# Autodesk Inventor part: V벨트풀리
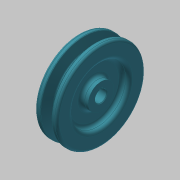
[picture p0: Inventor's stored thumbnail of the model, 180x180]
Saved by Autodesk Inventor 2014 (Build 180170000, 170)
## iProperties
Created: 2015-11
Part Number: V벨트풀리
Material: 강철, 탄소
Document SubType Name: Modeling
Designer: mduedu
Density: 1 g/cm^3
Appearance: Cadet Blue
Author: mduedu
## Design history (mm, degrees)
sketch "스케치1"
  geometry: L1 (-9.5, 0)-(9.5, 0); L2 (0, 0)-(0, 37.7); L3 (-4.825, 37.7)-(-9.5, 37.7); L4 (-9.5, 37.7)-(-9.5, 0); L5 (0, 28.7)-(-2.074, 28.7); L6 (-2.074, 28.7)-(-4.825, 37.7); L7 (4.825, 37.7)-(9.5, 37.7); L8 (9.5, 37.7)-(9.5, 0); L9 (0, 28.7)-(2.074, 28.7); L10 (2.074, 28.7)-(4.825, 37.7); L11 (-9.5, 35)-(9.5, 35); 3 further points
  constraints: 22 end point, 7 point on line, 4 perpendicular, 3 symmetric about line, 1 coincident, 1 horizontal, 1 horizontal alignment, 1 midpoint, 1 vertical
  dimensions: "d0" = 19 distance of L1.start L1.end; "d2" = 75.4 diameter of L2.end L1 (derived); "d3" = 34 deg angle of L10 L6; "d4" = 6.3 distance between parallel lines of L11 L9; "d5" = 2.7 distance between parallel lines of L7 L11; "d6" = 8 distance of point (4, 35) point (-4, 35); "d7" = 70 diameter of L11 L1
revolve "회전1" sketch "스케치1" stored, may be unused: angle "d8" = 90 deg
sketch "스케치2"
  geometry: C1 r 24 at (0, 0); C2 r 11 at (0, 0); 1 further point
  constraints: 2 centre point, 2 coincident
  dimensions: "d9" = 48 diameter of C1; "d10" = 22 diameter of C2
extrude "돌출1" cut sketch "스케치2" distance "d11" = 6; taper "d12" = 0 deg
fillet "모깎기1" dims "d13" = 3
fillet "모깎기2" dims "d14" = 3
fillet "모깎기3" dims "d15" = 1, "d16" = 0.5, "d17" = 2
hole "구멍1" diameter "d20" = 10; stored, may be unused: countersink angle "d24" = 90 deg, drill point angle "d26" = 118 deg; dims "d18" = 10, "d19" = 10, "d21" = 6, "d22" = 4, "d23" = 2, "d25" = 8
sketch "스케치3"
  geometry: L1 (-1.5, 0)-(1.5, 0); L2 (1.5, 0)-(1.5, 6.4); L3 (1.5, 6.4)-(-1.5, 6.4); L4 (-1.5, 6.4)-(-1.5, 0); 2 further points
  constraints: 8 end point, 2 parallel, 1 coincident, 1 horizontal, 1 midpoint, 1 perpendicular
  dimensions: "d27" = 3 distance of L2.end L3.end; "d29" = 6.4 distance of L3.end L1.start
extrude "돌출2" cut sketch "스케치3" stored distance "d30" = 6; taper "d31" = 0 deg
chamfer "모따기1" distance "d32" = 0.5; stored, may be unused: second distance "d33" = 2, angle "d34" = 45 deg
node "솔리드1"
mirror "대칭1"
